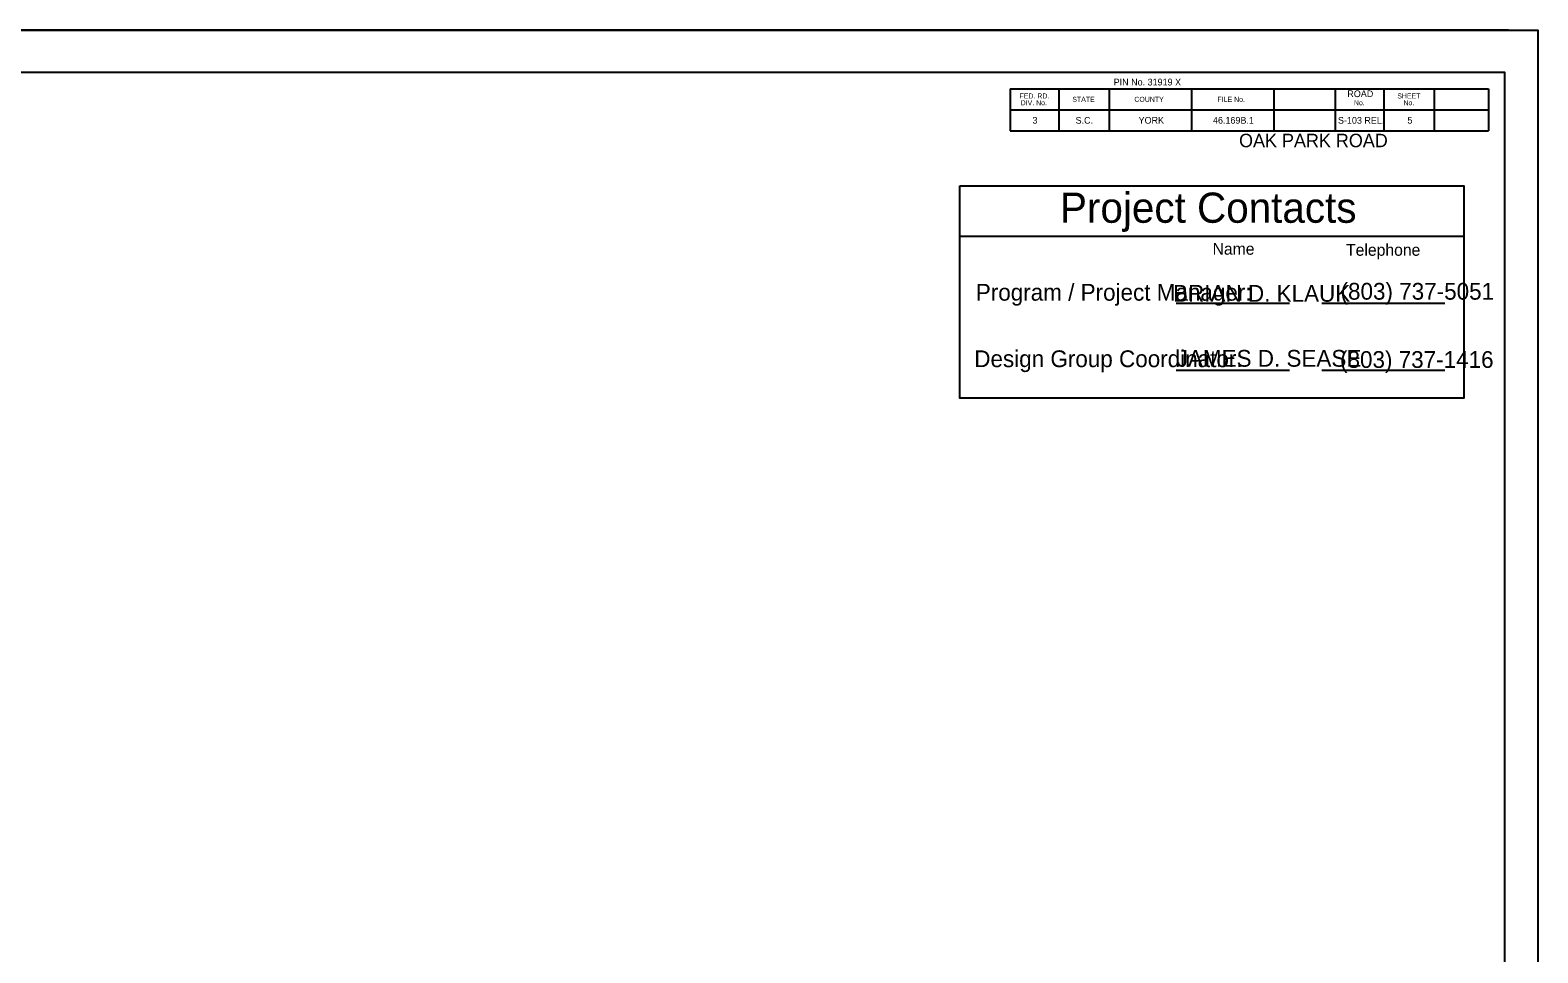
# Model space of a CAD drawing. Extents: x -796 to 2793, y -4650 to 4425.
# Drawn here: x 1879 to 2777, y -2950 to -2400 of the extents above; entities that cross this region are included whole.
import ezdxf

# ---------------------------------------------------------------- set-up
doc = ezdxf.new("R2010")
doc.units = 0
for name, color, linetype in [('RD_HC_CL', 7, 'Continuous'), ('RD_HC_Data', 7, 'Continuous'), ('RD_HC_Data_Tic', 7, 'Continuous'), ('RD_SHT_Bndy', 7, 'Continuous'), ('RD_TX_Misc1', 7, 'Continuous')]:
    doc.layers.add(name, color=color, linetype=linetype)

msp = doc.modelspace()

# ---------------------------------------------------------------- linework, layer by layer
at = {"layer": 'RD_HC_CL'}
msp.add_lwpolyline([(981.4, -2400), (2777.4, -2400), (2777.4, -3500), (981.4, -3500)], close=True, dxfattribs=at)
at = {"layer": 'RD_HC_Data'}
for p, q in [((2760, -2400), (1000, -2400)), ((1000, -2400), (2760, -2400)), ((2463.1, -2435), (2463.1, -2460)), ((2463.1, -2435), (2748.1, -2435)), ((2492.1, -2435), (2492.1, -2460)), ((2522.1, -2435), (2522.1, -2460)), ((2571.1, -2435), (2571.1, -2460)), ((2620.1, -2435), (2620.1, -2460)), ((2656.6, -2435), (2656.6, -2460)), ((2685.6, -2435), (2685.6, -2460)), ((2715.6, -2435), (2715.6, -2460)), ((2748.1, -2435), (2748.1, -2460)), ((2463.1, -2447.5), (2748.1, -2447.5)), ((2463.1, -2460), (2748.1, -2460))]:
    msp.add_line(p, q, dxfattribs=at)
msp.add_lwpolyline([(1082.6, -2425), (2757.6, -2425), (2757.6, -3475), (1082.6, -3475)], close=True, dxfattribs=at)
at = {"layer": 'RD_TX_Misc1'}
for p, q in [((2433.16, -2522.72), (2733.34, -2522.72)), ((2562.03, -2562.72), (2629.41, -2562.72)), ((2648.83, -2562.72), (2721.92, -2562.72)), ((2562.03, -2602.72), (2629.41, -2602.72)), ((2648.83, -2602.72), (2721.92, -2602.72))]:
    msp.add_line(p, q, dxfattribs=at)
msp.add_lwpolyline([(2433.16, -2492.72), (2733.34, -2492.72), (2733.34, -2619.29), (2433.16, -2619.29)], close=True, dxfattribs=at)

# ---------------------------------------------------------------- texts
at = {"layer": 'RD_HC_Data_Tic'}
for s, height, p in [('PIN No. 31919 X   ', 4, (2524.75, -2432.98)), ('FED. RD.', 3, (2468.72, -2440.73)), ('DIV. No.', 3, (2469.34, -2444.77)), ('STATE', 3, (2500.12, -2442.75)), ('COUNTY', 3, (2537.09, -2442.75)), ('FILE No.', 3, (2586.6, -2442.75)), ('      ROAD      ', 4, (2655.02, -2439.93)), ('No.', 3, (2667.86, -2444.77)), ('SHEET', 3, (2693.68, -2440.73)), ('No.', 3, (2697.36, -2444.77)), ('3', 4, (2476.4, -2455.75)), ('S.C.', 4, (2502.08, -2455.75)), ('      YORK      ', 4, (2530.68, -2455.75)), ('   46.169B.1    ', 4, (2579.44, -2455.75)), ('   S-103 REL.   ', 4, (2653.88, -2455.75)), ('       5        ', 4, (2689.34, -2455.75)), ('OAK PARK ROAD                 ', 8, (2599.44, -2469.78))]:
    msp.add_text(s, height=height, dxfattribs=at).set_placement(p)
at = {"layer": 'RD_SHT_Bndy'}
for s, p in [('(803) 737-5051', (2659.89, -2560.66)), ('BRIAN D. KLAUK', (2560.14, -2561.89)), ('JAMES D. SEASE', (2562.29, -2600.63)), ('(803) 737-1416', (2659.58, -2601.34))]:
    msp.add_text(s, height=10, dxfattribs=at).set_placement(p)
at = {"layer": 'RD_TX_Misc1'}
for s, height, p in [('Project Contacts', 18, (2492.81, -2514.83)), ('Name', 7, (2583.65, -2533.86)), ('Telephone', 7, (2663.17, -2534.49)), ('Program / Project Manager:', 10, (2442.65, -2561.26)), ('Design Group Coordinator:', 10, (2441.73, -2600.88))]:
    msp.add_text(s, height=height, dxfattribs=at).set_placement(p)

doc.saveas('drawing.dxf')
